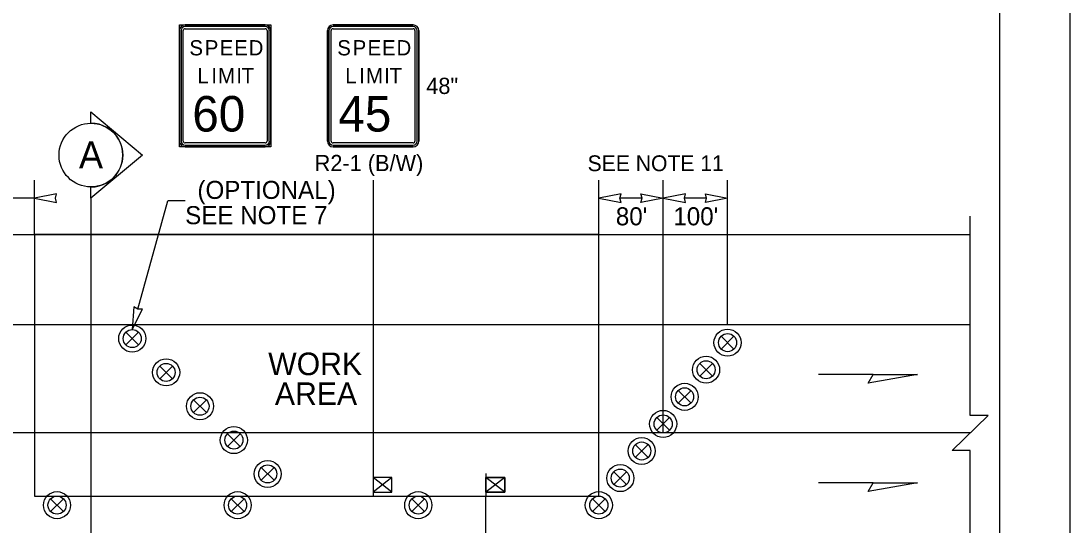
# Model space of a CAD drawing. Extents: x 99999 to 100116, y 99995 to 100013.
# Drawn here: x 100011.416 to 100016.062, y 100005.708 to 100007.941 of the extents above; entities that cross this region are included whole.
import ezdxf

# ---------------------------------------------------------------- set-up
doc = ezdxf.new("R2010")
doc.units = 0
for name, color, linetype in [('RD_ED_ShoulderPavedEdge', 7, 'Continuous'), ('RD_MK_LineEdgeYellow', 7, 'Continuous'), ('RD_MK_LineLane', 7, 'Continuous'), ('SH_GI_PlotLimits', 7, 'Continuous'), ('SH_GI_SheetBorder', 7, 'Continuous'), ('SH_TI_WZSectionCut', 7, 'Continuous'), ('TR_SN_ConstructionSigns', 7, 'Continuous'), ('TR_WZ_PortableSignMount5ftMinBlk-Org', 7, 'Continuous'), ('TR_WZ_PortableSignMount5ftMinBlk-Wht', 7, 'Continuous'), ('TR_WZ_TrafficSafetyDrum', 7, 'Continuous'), ('TR_WZ_WorkAreaLabel', 7, 'Continuous'), ('TR_WZ_WorkZoneDetails', 7, 'Continuous'), ('TR_WZ_WorkZoneTextCurrent', 7, 'Continuous')]:
    doc.layers.add(name, color=color, linetype=linetype)

msp = doc.modelspace()

# ---------------------------------------------------------------- linework, layer by layer
at = {"layer": 'RD_ED_ShoulderPavedEdge'}
msp.add_line((100000.8283, 100006.9957), (100015.62, 100006.9957), dxfattribs=at)
at = {"layer": 'RD_MK_LineEdgeYellow'}
msp.add_line((100000.8283, 100006.5957), (100015.62, 100006.5957), dxfattribs=at)
at = {"layer": 'RD_MK_LineLane'}
msp.add_lwpolyline([(100015.62, 100006.1157), (100000.8283, 100006.1157)], dxfattribs=at)
at = {"layer": 'SH_GI_PlotLimits'}
msp.add_lwpolyline([(99999.0625, 99999.6875), (100016.0625, 99999.6875), (100016.0625, 100010.6875), (99999.0625, 100010.6875)], close=True, dxfattribs=at)
at = {"layer": 'SH_GI_SheetBorder'}
msp.add_line((100015.75, 100010.375), (100015.75, 100000), dxfattribs=at)
at = {"layer": 'SH_TI_WZSectionCut'}
for p, q in [((100011.7253, 100007.4881), (100011.7253, 100007.538)), ((100011.7253, 100007.538), (100011.9534, 100007.3469)), ((100011.9534, 100007.3469), (100011.7253, 100007.1557)), ((100011.7253, 100007.1557), (100011.7253, 100007.2056)), ((100011.7253, 100007.1557), (100011.7253, 100005.0757))]:
    msp.add_line(p, q, dxfattribs=at)
msp.add_circle((100011.7253, 100007.3469), 0.1412, dxfattribs=at)
msp.add_arc((100011.7253, 100007.3469), 0.1412, 269.9978, 90.0022, dxfattribs=at)
at = {"layer": 'TR_SN_ConstructionSigns'}
for p, q in [((100012.1178, 100007.409), (100012.1178, 100007.8984)), ((100012.1178, 100007.8984), (100012.1178, 100007.409)), ((100012.1248, 100007.8984), (100012.1248, 100007.409)), ((100012.1347, 100007.409), (100012.1347, 100007.8984)), ((100012.1431, 100007.9237), (100012.4975, 100007.9237)), ((100012.4975, 100007.9237), (100012.1431, 100007.9237)), ((100012.4975, 100007.9167), (100012.1431, 100007.9167)), ((100012.1431, 100007.9069), (100012.4975, 100007.9069)), ((100012.5059, 100007.8984), (100012.5059, 100007.409)), ((100012.5157, 100007.409), (100012.5157, 100007.8984)), ((100012.5228, 100007.8984), (100012.5228, 100007.409)), ((100012.5228, 100007.409), (100012.5228, 100007.8984)), ((100012.7728, 100007.409), (100012.7728, 100007.8984)), ((100012.7728, 100007.8984), (100012.7728, 100007.409)), ((100012.7798, 100007.8984), (100012.7798, 100007.409)), ((100012.7897, 100007.409), (100012.7897, 100007.8984)), ((100012.7981, 100007.9237), (100013.1525, 100007.9237)), ((100013.1525, 100007.9237), (100012.7981, 100007.9237)), ((100013.1525, 100007.9167), (100012.7981, 100007.9167)), ((100012.7981, 100007.9069), (100013.1525, 100007.9069)), ((100013.1609, 100007.8984), (100013.1609, 100007.409)), ((100013.1707, 100007.409), (100013.1707, 100007.8984)), ((100013.1778, 100007.8984), (100013.1778, 100007.409)), ((100013.1778, 100007.409), (100013.1778, 100007.8984)), ((100012.4975, 100007.4006), (100012.1431, 100007.4006)), ((100012.1431, 100007.3908), (100012.4975, 100007.3908)), ((100012.4975, 100007.3837), (100012.1431, 100007.3837)), ((100012.1431, 100007.3837), (100012.4975, 100007.3837)), ((100013.1525, 100007.4006), (100012.7981, 100007.4006)), ((100012.7981, 100007.3908), (100013.1525, 100007.3908)), ((100013.1525, 100007.3837), (100012.7981, 100007.3837)), ((100012.7981, 100007.3837), (100013.1525, 100007.3837))]:
    msp.add_line(p, q, dxfattribs=at)
msp.add_lwpolyline([(100012.1178, 100007.9237), (100012.5228, 100007.9237), (100012.5228, 100007.3837), (100012.1178, 100007.3837)], close=True, dxfattribs=at)
for centre, radius, start, end in [((100012.1431, 100007.8984), 0.0253, 90, 180), ((100012.1431, 100007.8984), 0.0253, 90, 180), ((100012.1431, 100007.8984), 0.0183, 90, 180), ((100012.1431, 100007.8984), 0.00844, 90, 180), ((100012.4975, 100007.8984), 0.0253, 360, 90), ((100012.4975, 100007.8984), 0.0253, 360, 90), ((100012.4975, 100007.8984), 0.0183, 0, 90), ((100012.4975, 100007.8984), 0.00844, 360, 90), ((100012.7981, 100007.8984), 0.0253, 90, 180), ((100012.7981, 100007.8984), 0.0253, 90, 180), ((100012.7981, 100007.8984), 0.0183, 90, 180), ((100012.7981, 100007.8984), 0.00844, 90, 180), ((100013.1525, 100007.8984), 0.0253, 360, 90), ((100013.1525, 100007.8984), 0.0253, 360, 90), ((100013.1525, 100007.8984), 0.0183, 0, 90), ((100013.1525, 100007.8984), 0.00844, 360, 90), ((100012.1431, 100007.409), 0.0253, 180, 270), ((100012.1431, 100007.409), 0.0253, 180, 270), ((100012.1431, 100007.409), 0.0183, 180, 270), ((100012.1431, 100007.409), 0.00844, 180, 270), ((100012.4975, 100007.409), 0.0253, 270, 360), ((100012.4975, 100007.409), 0.0183, 270, 360), ((100012.4975, 100007.409), 0.00844, 270, 0), ((100012.4975, 100007.409), 0.0253, 270, 360), ((100012.7981, 100007.409), 0.0253, 180, 270), ((100012.7981, 100007.409), 0.0253, 180, 270), ((100012.7981, 100007.409), 0.0183, 180, 270), ((100012.7981, 100007.409), 0.00844, 180, 270), ((100013.1525, 100007.409), 0.0253, 270, 360), ((100013.1525, 100007.409), 0.0183, 270, 360), ((100013.1525, 100007.409), 0.00844, 270, 0), ((100013.1525, 100007.409), 0.0253, 270, 360)]:
    msp.add_arc(centre, radius, start, end, dxfattribs=at)
at = {"layer": 'TR_WZ_PortableSignMount5ftMinBlk-Org'}
for p, q in [((100013.4753, 100005.9357), (100013.4753, 100005.8357)), ((100013.5587, 100005.8532), (100013.4753, 100005.9182)), ((100013.5587, 100005.9182), (100013.4753, 100005.8532)), ((100013.517, 100005.8857), (100013.517, 100005.8857)), ((100013.5171, 100005.8857), (100013.5171, 100005.8857))]:
    msp.add_line(p, q, dxfattribs=at)
for points in [[(100013.5587, 100005.8532), (100013.5587, 100005.9182), (100013.4753, 100005.9182), (100013.4753, 100005.8532)], [(100013.4753, 100005.9182), (100013.5587, 100005.9182), (100013.5587, 100005.8532), (100013.4753, 100005.8532)]]:
    msp.add_lwpolyline(points, close=True, dxfattribs=at)
at = {"layer": 'TR_WZ_PortableSignMount5ftMinBlk-Wht'}
for p, q in [((100012.9753, 100005.9357), (100012.9753, 100005.8357)), ((100013.0587, 100005.8532), (100012.9753, 100005.9182)), ((100013.0587, 100005.9182), (100012.9753, 100005.8532)), ((100013.017, 100005.8857), (100013.017, 100005.8857)), ((100013.0171, 100005.8857), (100013.0171, 100005.8857))]:
    msp.add_line(p, q, dxfattribs=at)
msp.add_lwpolyline([(100013.0587, 100005.8532), (100013.0587, 100005.9182), (100012.9753, 100005.9182), (100012.9753, 100005.8532)], close=True, dxfattribs=at)
at = {"layer": 'TR_WZ_TrafficSafetyDrum'}
for p, q in [((100011.9369, 100006.5623), (100011.8803, 100006.5057)), ((100011.8803, 100006.5623), (100011.9369, 100006.5057)), ((100014.5171, 100006.4875), (100014.5737, 100006.5441)), ((100014.5737, 100006.4875), (100014.5171, 100006.5441)), ((100012.0869, 100006.4123), (100012.0303, 100006.3557)), ((100012.0303, 100006.4123), (100012.0869, 100006.3557)), ((100014.4221, 100006.3675), (100014.4786, 100006.424)), ((100014.4786, 100006.3675), (100014.4221, 100006.424)), ((100014.3271, 100006.2475), (100014.3836, 100006.304)), ((100014.3836, 100006.2475), (100014.3271, 100006.304)), ((100012.2369, 100006.2623), (100012.1803, 100006.2057)), ((100012.1803, 100006.2623), (100012.2369, 100006.2057)), ((100014.232, 100006.1274), (100014.2886, 100006.184)), ((100014.2886, 100006.1274), (100014.232, 100006.184)), ((100012.3869, 100006.1123), (100012.3303, 100006.0557)), ((100012.3303, 100006.1123), (100012.3869, 100006.0557)), ((100014.137, 100006.0074), (100014.1936, 100006.064)), ((100014.1936, 100006.0074), (100014.137, 100006.064)), ((100012.5369, 100005.9623), (100012.4803, 100005.9057)), ((100012.4803, 100005.9623), (100012.5369, 100005.9057)), ((100014.042, 100005.8874), (100014.0986, 100005.944)), ((100014.0986, 100005.8874), (100014.042, 100005.944)), ((100011.547, 100005.7674), (100011.6036, 100005.824)), ((100011.6036, 100005.7674), (100011.547, 100005.824)), ((100012.347, 100005.7674), (100012.4036, 100005.824)), ((100012.4036, 100005.7674), (100012.347, 100005.824)), ((100013.147, 100005.7674), (100013.2036, 100005.824)), ((100013.2036, 100005.7674), (100013.147, 100005.824)), ((100013.947, 100005.7674), (100014.0036, 100005.824)), ((100014.0036, 100005.7674), (100013.947, 100005.824))]:
    msp.add_line(p, q, dxfattribs=at)
for centre, radius in [((100011.9086, 100006.534), 0.06), ((100011.9086, 100006.534), 0.06), ((100011.9086, 100006.534), 0.04), ((100014.5454, 100006.5158), 0.06), ((100014.5454, 100006.5158), 0.06), ((100014.5454, 100006.5158), 0.04), ((100014.4504, 100006.3958), 0.06), ((100014.4504, 100006.3958), 0.06), ((100012.0586, 100006.384), 0.06), ((100012.0586, 100006.384), 0.06), ((100012.0586, 100006.384), 0.04), ((100014.4504, 100006.3958), 0.04), ((100014.3553, 100006.2757), 0.06), ((100014.3553, 100006.2757), 0.06), ((100014.3553, 100006.2757), 0.04), ((100012.2086, 100006.234), 0.06), ((100012.2086, 100006.234), 0.06), ((100012.2086, 100006.234), 0.04), ((100014.2603, 100006.1557), 0.06), ((100014.2603, 100006.1557), 0.06), ((100014.2603, 100006.1557), 0.04), ((100012.3586, 100006.084), 0.06), ((100012.3586, 100006.084), 0.06), ((100012.3586, 100006.084), 0.04), ((100014.1653, 100006.0357), 0.06), ((100014.1653, 100006.0357), 0.06), ((100014.1653, 100006.0357), 0.04), ((100012.5086, 100005.934), 0.06), ((100012.5086, 100005.934), 0.06), ((100012.5086, 100005.934), 0.04), ((100014.0703, 100005.9157), 0.06), ((100014.0703, 100005.9157), 0.06), ((100014.0703, 100005.9157), 0.04), ((100011.5753, 100005.7957), 0.06), ((100011.5753, 100005.7957), 0.06), ((100012.3753, 100005.7957), 0.06), ((100012.3753, 100005.7957), 0.06), ((100013.1753, 100005.7957), 0.06), ((100013.1753, 100005.7957), 0.06), ((100013.9753, 100005.7957), 0.06), ((100013.9753, 100005.7957), 0.06), ((100011.5753, 100005.7957), 0.04), ((100012.3753, 100005.7957), 0.04), ((100013.1753, 100005.7957), 0.04), ((100013.9753, 100005.7957), 0.04)]:
    msp.add_circle(centre, radius, dxfattribs=at)
at = {"layer": 'TR_WZ_WorkZoneDetails'}
for p, q in [((100011.4753, 100006.9957), (100011.4753, 100007.2357)), ((100012.9753, 100007.2357), (100012.9753, 100005.9357)), ((100013.9753, 100005.8357), (100013.9753, 100007.2357)), ((100014.2603, 100006.1157), (100014.2603, 100007.2357)), ((100014.5454, 100006.5957), (100014.5454, 100007.2357)), ((100011.4753, 100007.1557), (100011.1674, 100007.1557)), ((100014.1666, 100007.1557), (100014.069, 100007.1557)), ((100014.4516, 100007.1557), (100014.3541, 100007.1557)), ((100011.9336, 100006.6644), (100012.0668, 100007.1447)), ((100012.143, 100007.1447), (100012.0668, 100007.1447)), ((100015.19, 100006.375), (100014.9489, 100006.375)), ((100015.19, 100005.895), (100014.9489, 100005.895)), ((100013.4753, 100004.9157), (100013.4753, 100005.8357))]:
    msp.add_line(p, q, dxfattribs=at)
for points in [[(100011.4753, 100007.1557), (100011.5736, 100007.1365), (100011.569, 100007.1557), (100011.5736, 100007.175)], [(100013.9753, 100007.1557), (100014.0736, 100007.1365), (100014.069, 100007.1557), (100014.0736, 100007.175)], [(100014.2603, 100007.1557), (100014.162, 100007.1365), (100014.1666, 100007.1557), (100014.162, 100007.175)], [(100014.2603, 100007.1557), (100014.3586, 100007.1365), (100014.3541, 100007.1557), (100014.3586, 100007.175)], [(100014.5454, 100007.1557), (100014.4471, 100007.1365), (100014.4516, 100007.1557), (100014.4471, 100007.175)], [(100011.4753, 100006.9957), (100011.4753, 100005.8357), (100013.9753, 100005.8357), (100013.9753, 100006.9957)], [(100011.9086, 100006.574), (100011.9534, 100006.6636), (100011.9336, 100006.6644), (100011.9162, 100006.6739)], [(100015.3865, 100006.375), (100015.1677, 100006.3364), (100015.19, 100006.375)], [(100015.3865, 100005.895), (100015.1677, 100005.8564), (100015.19, 100005.895)]]:
    msp.add_lwpolyline(points, close=True, dxfattribs=at)
msp.add_lwpolyline([(100015.62, 100005.1557), (100015.62, 100006.0383), (100015.5399, 100006.0383), (100015.7, 100006.1932), (100015.62, 100006.1932), (100015.62, 100007.0757)], dxfattribs=at)

# ---------------------------------------------------------------- texts
at = {"layer": 'SH_TI_WZSectionCut'}
msp.add_text('A', height=0.12, rotation=359.99, dxfattribs=at).set_placement((100011.6723, 100007.2877))
at = {"layer": 'TR_SN_ConstructionSigns'}
for s, height, p in [('S', 0.0675, (100012.1617, 100007.7887)), ('P', 0.0675, (100012.2298, 100007.7887)), ('E', 0.0675, (100012.296, 100007.7887)), ('E', 0.0675, (100012.3601, 100007.7887)), ('D', 0.0675, (100012.4242, 100007.7887)), ('S', 0.0675, (100012.8167, 100007.7887)), ('P', 0.0675, (100012.8848, 100007.7887)), ('E', 0.0675, (100012.951, 100007.7887)), ('E', 0.0675, (100013.0151, 100007.7887)), ('D', 0.0675, (100013.0792, 100007.7887)), ('L', 0.0675, (100012.1968, 100007.665)), ('I', 0.0675, (100012.2589, 100007.665)), ('M', 0.0675, (100012.2886, 100007.665)), ('I', 0.0675, (100012.3696, 100007.665)), ('T', 0.0675, (100012.3932, 100007.665)), ('L', 0.0675, (100012.8518, 100007.665)), ('I', 0.0675, (100012.9139, 100007.665)), ('M', 0.0675, (100012.9436, 100007.665)), ('I', 0.0675, (100013.0246, 100007.665)), ('T', 0.0675, (100013.0482, 100007.665)), ('48"', 0.072, (100013.211, 100007.6177)), ('R2-1 (B/W)', 0.072, (100012.7165, 100007.2757))]:
    msp.add_text(s, height=height, rotation=360, dxfattribs=at).set_placement(p)
for s, p in [('60', (100012.1747, 100007.4512)), ('45', (100012.8218, 100007.4512))]:
    msp.add_text(s, height=0.1575, dxfattribs=at).set_placement(p)
at = {"layer": 'TR_WZ_WorkAreaLabel'}
for s, p in [('WORK', (100012.5107, 100006.3718)), ('AREA', (100012.5404, 100006.2397))]:
    msp.add_text(s, height=0.1, dxfattribs=at).set_placement(p)
at = {"layer": 'TR_WZ_WorkZoneTextCurrent'}
for s, height, p in [('SEE NOTE 11', 0.07, (100013.9255, 100007.2757)), ('(OPTIONAL)', 0.08, (100012.1974, 100007.1527)), ('SEE NOTE 7', 0.08, (100012.143, 100007.0407)), ("80'", 0.08, (100014.0506, 100007.0357)), ("100'", 0.08, (100014.3054, 100007.0357))]:
    msp.add_text(s, height=height, dxfattribs=at).set_placement(p)

doc.saveas('drawing.dxf')
